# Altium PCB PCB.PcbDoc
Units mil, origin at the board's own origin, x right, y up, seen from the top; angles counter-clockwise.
Board outline 1889.76 x 2283.46 mil, 2 copper layers (Top Layer, Bottom Layer); 37 components, 25 nets, 145 pads, 86 vias.
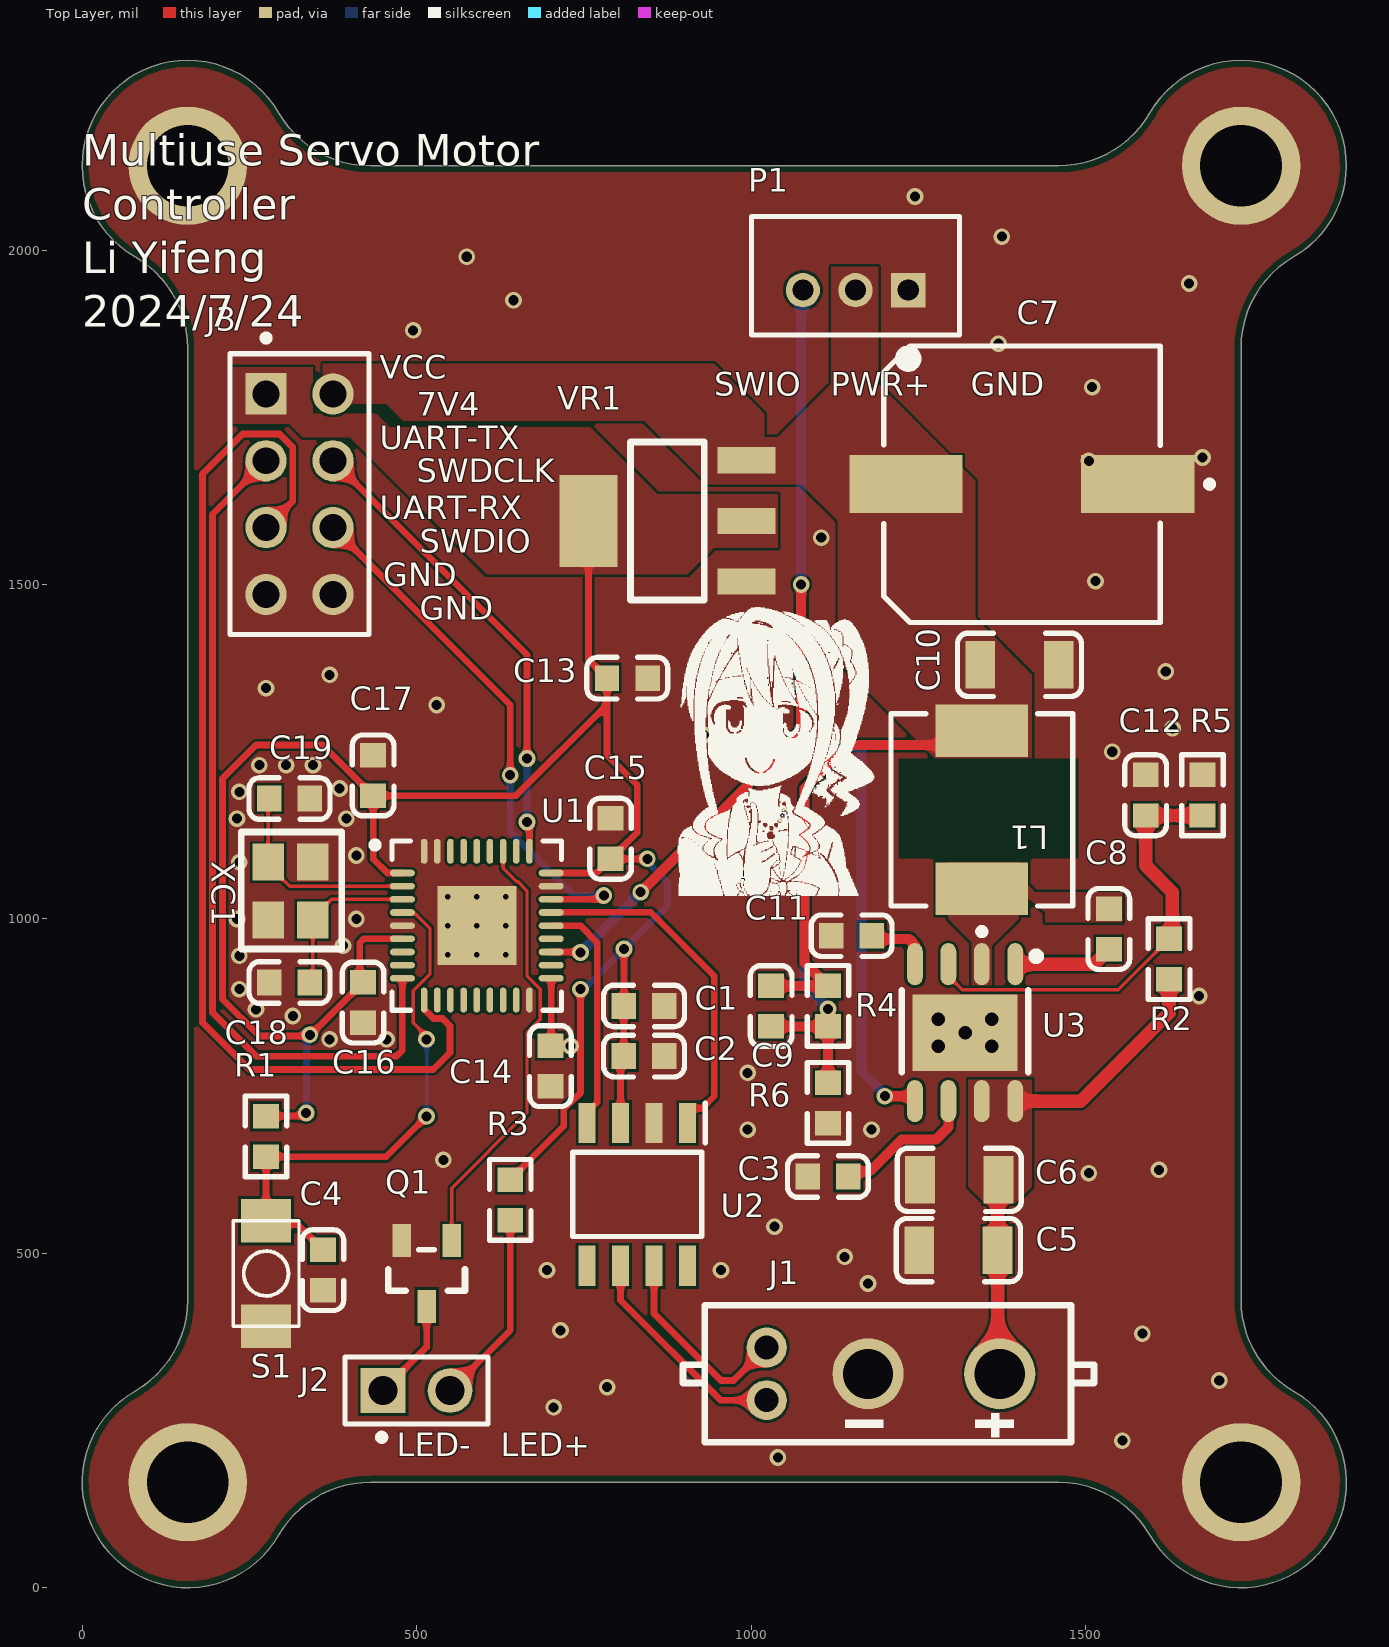
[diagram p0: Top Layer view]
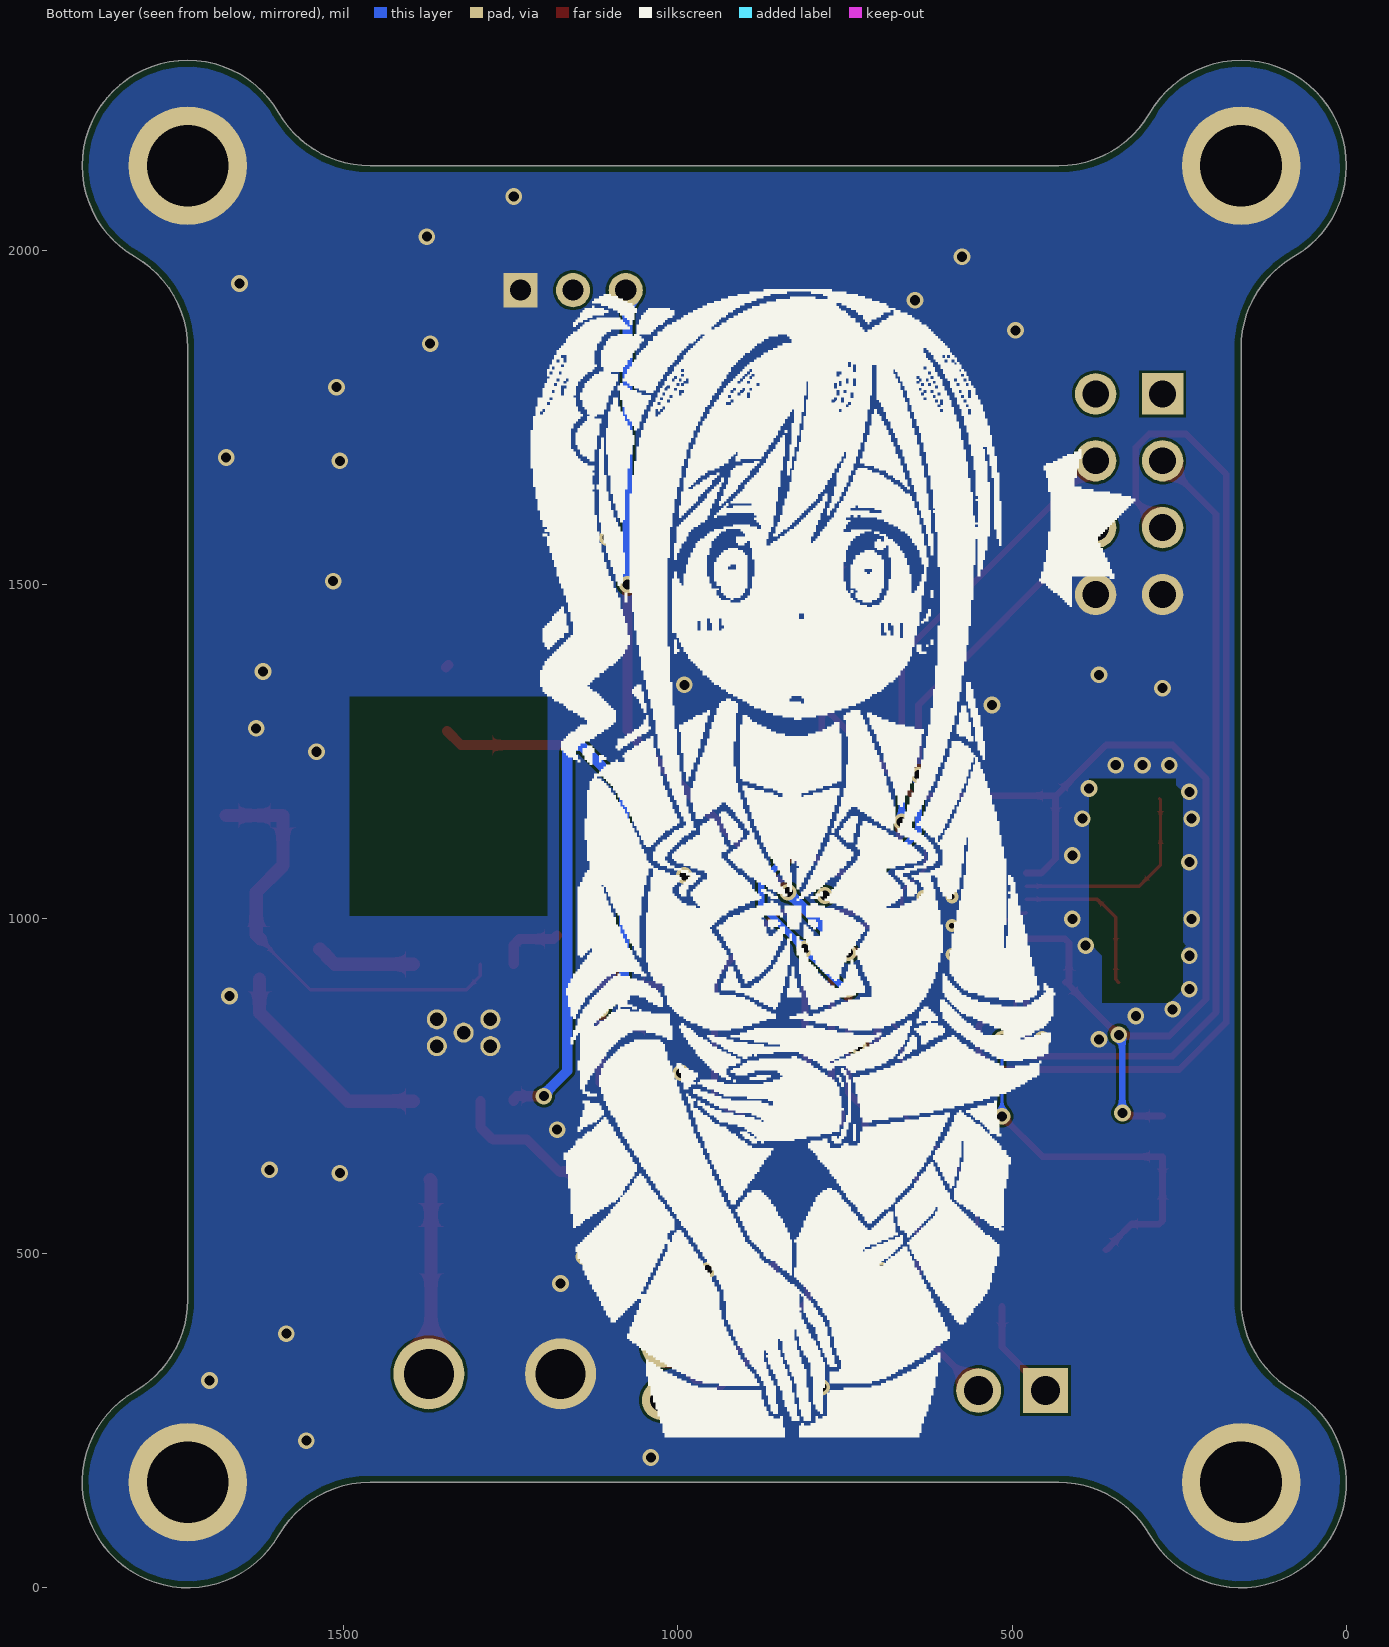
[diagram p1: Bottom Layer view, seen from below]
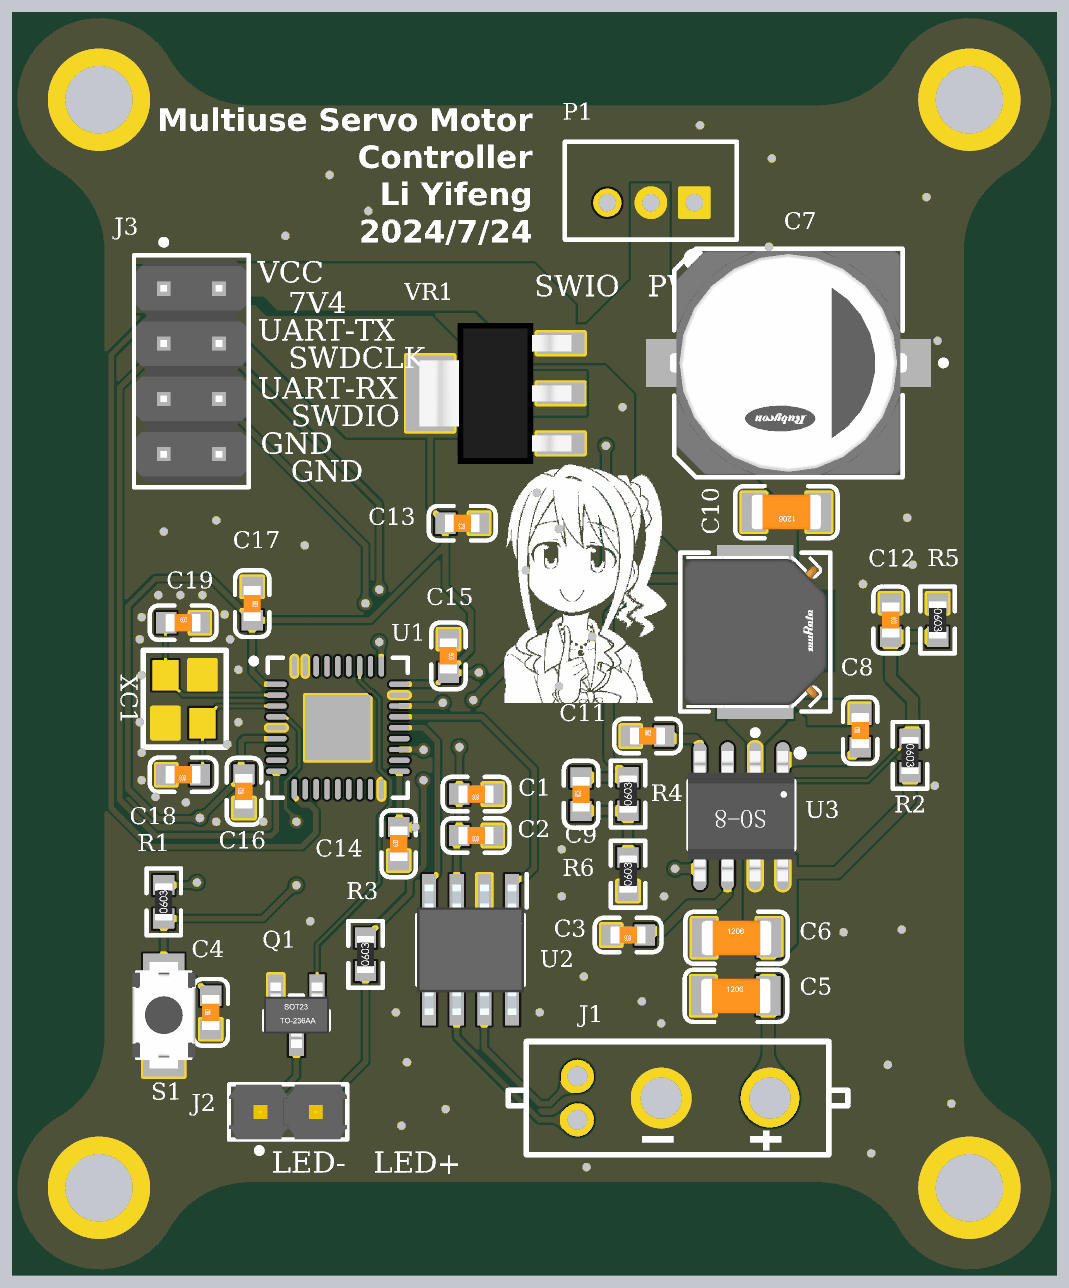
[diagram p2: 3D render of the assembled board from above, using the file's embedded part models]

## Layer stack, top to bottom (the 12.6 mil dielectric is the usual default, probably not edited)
Top Solder: solder mask 0.4, Solder Resist, Dk 3.5
Top Layer: signal copper 1.4
Dielectric 1: dielectric 12.6, FR-4, Dk 4.8
Bottom Layer: signal copper 1.4
Bottom Solder: solder mask 0.4, Solder Resist, Dk 3.5

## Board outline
294.11,78.99 cw(c157.73,157.73) 78.99,294.11 ccw(c0.25,430.49) 157.73,430.49 157.73,1853.47 ccw(c0.25,1853.47) 78.99,1989.85 cw(c157.73,2126.23) 294.11,2204.97 ccw(c430.49,2283.71) 430.49,2126.23 1459.77,2126.23 ccw(c1459.77,2283.71) 1596.15,2204.97 cw(c1732.53,2126.23) 1811.27,1989.85 ccw(c1890.01,1853.47) 1732.53,1853.47 1732.53,430.49 ccw(c1890.01,430.49) 1811.27,294.11 cw(c1732.53,157.73) 1596.15,78.99 ccw(c1459.77,0.25) 1459.77,157.73 430.49,157.73 ccw(c430.49,0.25)

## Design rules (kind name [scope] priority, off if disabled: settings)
BoardOutlineClearance BoardOutlineClearance_1 [All] p1: gap=10 ignorepadtopadclearanceinfootprint=FALSE except(0: Arc-SplitContinuation Track-SplitContinuation SMDPad-SplitContinuation THPad-SplitContinuation Via-SplitContinuation Fill-SplitContinuation Poly-SplitContinuation Region-SplitContinuation Text-SplitContinuation)
Clearance Clearance_1 [OnMid vs OnMid] p1: gap=4 ignorepadtopadclearanceinfootprint=FALSE sourcerule=42 cellrowname=All cellrowtype=0 cellcolname=All cellcoltype=0 innerlayers=TRUE
Clearance Clearance_2 [(ExistsOnLayer('Top Layer') Or ExistsOnLayer('Bottom Layer')) vs (ExistsOnLayer('Top Layer') Or ExistsOnLayer('Bottom Layer'))] p2: gap=4 ignorepadtopadclearanceinfootprint=FALSE sourcerule=42 cellrowname=All cellrowtype=0 cellcolname=All cellcoltype=0 outerlayers=TRUE
Clearance [All] p3: gap=10 ignorepadtopadclearanceinfootprint=FALSE ismatrix=TRUE
PolygonConnect [All] p1: connectstyle=Direct reliefconductorwidth=10 reliefentries=4 polygonreliefangle="90 Angle" airgapwidth=10
RoutingVias [All] p1: holewidth=15 width=25 viastyle="Through Hole" minholewidth=15 minwidth=25 maxholewidth=15 maxwidth=25
SolderMaskExpansion [All] p1: expansion=4 istentingtop=FALSE
SupplyNets "Schematic Supply Nets_3" [InNet('VCC')] p1: voltage=0.000
SupplyNets "Schematic Supply Nets_2" [InNet('7V4')] p2: voltage=0.000
SupplyNets "Schematic Supply Nets_1" [InNet('GND')] p3: voltage=0.000
SupplyNets "Schematic Supply Nets" [InNet('+24')] p4: voltage=0.000
Width "Schematic Width Constraint" [InNet('7V4')] p1: maxlimit=100 minlimit=5 preferedwidth=10 minimp=50.000000 maximp=50.000000 favimp=50.000000
Width [All] p2: maxlimit=100 minlimit=5 preferedwidth=10 minimp=50.000000 maximp=50.000000 favimp=50.000000
30 further rules are at their usual default settings.

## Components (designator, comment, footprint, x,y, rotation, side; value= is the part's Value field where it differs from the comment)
C1 "1uF (105) 10% 50V" 0603_C 840,870 r180 top
C2 "100nF (104) 10% 50V" 0603_C 840,795 r180 top
C3 "1uF (105) 10% 50V" 0603_C 1115,615 r180 top
C4 "100nF (104) 10% 50V" 0603_C 360,475 r90 top
C5 "10uF (106) 10% 50V" 1206_C 1310,505 r0 top
C6 "10uF (106) 10% 50V" 1206_C 1311.34,610 r0 top
C7 "50THV100M10X10.5" FP-THV10X10_5-MFG 1405,1650 r180 top
C8 "100nF (104) 10% 50V" 0603_C 1535,985 r90 top
C9 "100pF (101) 5% 50V" 0603_C 1030,869.68 r90 top
C10 "10uF (106) 10% 50V" 1206_C 1401.34,1380 r180 top
C11 "1uF (105) 10% 50V" 0603_C 1150.32,975 r0 top
C12 "1uF (105) 10% 50V" 0603_C 1590,1185 r270 top
C13 "1uF (105) 10% 50V" 0603_C 815,1360 r180 top
C14 "100nF (104) 10% 50V" 0603_C 700,780 r90 top
C15 "100nF (104) 10% 50V" 0603_C 790,1120 r270 top
C16 "100nF (104) 10% 50V" 0603_C 420,875 r90 top
C17 "100nF (104) 10% 50V" 0603_C 435,1214.68 r270 top
C18 "12pF (120) 5% 50V" 0603_C 310,905 r180 top
C19 "12pF (120) 5% 50V" 0603_C 310,1180 r0 top
J1 "XT30PB(2+2)-M" XT30PB(2+2)-M-Footprint-1 1262.61,332.36 r180 top
J2 "2211S-02G" FP-2211S-02G-MFG 500,295 r0 top
J3 "M20-9980446" FP-M20-9980446-MFG 325,1635 r270 top
L1 "FDSD0630-H-2R2M=P3" FP-FDSD0630-MFG 1345,1163.11 r90 top
P1 "B3B-PH-K-S(LF)(SN)" JST-B3B-PH-K-S-3_V 1156.26,1961.65 r180 top
Q1 "2N7002 7002" SOT-23(SOT-23-3) 515,470 r90 top
R1 "10KΩ (1002) ±1%" 0603_R 275,675 r90 top
R2 "10KΩ (1002) ±1%" 0603_R 1625,940 r270 top
R3 "1KΩ (1001) ±1%" 0603_R 640,580 r90 top
R4 "39KΩ (3902) ±1%" 0603_R 1115,870 r90 top
R5 "1KΩ (1001) ±1%" 0603_R 1675,1185 r270 top
R6 "3.3KΩ (3301) ±1%" 0603_R 1115,725 r90 top
S1 "按键" SWT3*4 275,470 r90 top
U1 "STM32F103TBU6" STM-VFQFPN36_L 590,990 r0 top
U2 "SN65HVD232D" SOIC127P600X175-8N 830,588.23 r270 top
U3 "SY8205FC" SOP-8_EP_150mil 1320,830 r180 top
VR1 "AMS1117-3.3" SOT-223 875,1595 r0 top
XC1 "3225 Passive Crystal" SMD-3225 278.07,1085 r270 top

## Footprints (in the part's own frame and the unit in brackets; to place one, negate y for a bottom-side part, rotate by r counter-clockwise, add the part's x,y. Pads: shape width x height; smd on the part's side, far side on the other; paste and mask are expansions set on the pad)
0603_C [mm]
  rect 0.93x0.98 smd: 1(-0.77,0) 2(0.77,0)
  silkscreen extent -1.53,-0.79 1.54,0.79, body extent -0.8,-0.4 0.8,0.4, height 0.3
0603_R [mm]
  rect 0.93x0.98 smd: 1(-0.77,0) 2(0.77,0)
  silkscreen extent -1.53,-0.79 1.54,0.79, body extent -0.85,-0.4 0.85,0.4, height 0.56
1206_C [mm]
  rect 1.13x1.8 smd: 1(-1.49,0) 2(1.49,0)
  silkscreen extent -2.36,-1.2 2.35,1.2, body extent -1.6,-0.81 1.6,0.79, height 1
FP-2211S-02G-MFG [mm]
  rect 1.7x1.7 hole 1.1 paste-2539.97 mask+0: 1(-1.27,0)
  round 1.7 hole 1.1 paste-2539.97 mask+0: 2(1.27,0)
  silkscreen extent -2.72,-1.9 2.72,1.27, body extent -2.82,-1.37 2.82,1.37, height 0.25
FP-FDSD0630-MFG [mm]
  rect 2x3.5 smd paste+0 mask+0: 1(-3,0) 2(3,0)
  silkscreen extent -4.75,-3.45 3.65,3.45, body extent -4.1,-3.55 4.1,3.55, height 0.25
FP-M20-9980446-MFG [mm]
  rect 1.57x1.57 hole 1.02 paste-2539.97 mask+0: 1(-3.81,-1.27)
  round 1.57 hole 1.02 paste-2539.97 mask+0: 2(-3.81,1.27) 3(-1.27,-1.27) 4(-1.27,1.27) 5(1.27,-1.27) 6(1.27,1.27) 7(3.81,-1.27) 8(3.81,1.27)
  silkscreen extent -6.05,-2.64 5.33,2.64, body extent -5.43,-2.74 5.43,2.74, height 0.25
FP-THV10X10_5-MFG [mm]
  rect 4.3x2.2 smd paste+0 mask+0: 1(-4.4,0) 2(4.4,0)
  silkscreen extent -7.25,-5.25 5.25,5.25, body extent -6.8,-5.5 6.8,5.5, height 0.25
JST-B3B-PH-K-S-3_V [mm] "Connector, 3-Leads, Body 7.9x4.5mm, Pitch 2mm"
  rect 1.3x1.3 hole 0.8: 1(-2,0.55)
  round 1.3 hole 0.8: 2(0,0.55) 3(2,0.55)
  silkscreen extent -3.95,-2.25 3.95,3.4, body extent -3.95,-2.25 3.95,2.25, height 6
SMD-3225 [mm]
  rect 1.4x1.2 smd paste-2539.97: 1(0,0) 2(2.2,0) 3(2.2,1.7) 4(0,1.7)
  silkscreen extent -1.14,-1.02 3.3,2.79
SOIC127P600X175-8N [mm]
  rect 1.525x0.65 smd: 1(-2.712,1.905) 2(-2.712,0.635) 3(-2.712,-0.635) 4(-2.712,-1.905) 5(2.712,-1.905) 6(2.712,-0.635) 7(2.712,0.635) 8(2.712,1.905)
  silkscreen extent -3.47,-2.45 1.6,2.58, body extent -3,-2.45 3,2.45, height 1.75
SOP-8_EP_150mil [mm]
  round 0.762 hole 0.508: 0(-1.016,-0.508) 0(-1.016,0.508) 0(0,0) 0(1.016,0.508) 0(1.016,-0.508)
  rect 4x2.9 smd: 0(0,0)
  oval 0.6x1.6 smd: 1(-1.905,-2.6) 2(-0.635,-2.6) 3(0.635,-2.6) 4(1.905,-2.6) 5(1.905,2.6) 6(0.635,2.6) 7(-0.635,2.6) 8(-1.905,2.6)
  silkscreen extent -2.85,-3.05 2.4,1.5, body extent -2.45,-3 2.45,3
SOT-23(SOT-23-3) [mm]
  rect 1.25x0.7 smd: 1(1.25,-0.95) 2(1.25,0.95) 3(-1.25,0)
  silkscreen extent -0.65,-1.46 0.9,1.46, body extent -1.5,-1.5 1.5,1.5, height 1.3
SOT-223 [mm]
  rect 2.2x1 smd: 1(3,-2.3) 2(3,0) 3(3,2.3)
  rect 2.2x3.5 smd: 2(-3,0)
  silkscreen extent -1.4,-3 1.4,3, body extent -3.49,-3.24 3.49,3.24, height 1.64
STM-VFQFPN36_L [mm] "QFN, 36-Leads, Body 6.13x6.13mm, Pitch 0.5mm, Thermal Pad 3x3mm, IPC High Density"
  oval 0.95x0.25 smd: 1(-2.825,2) 2(-2.825,1.5) 3(-2.825,1) 4(-2.825,0.5) 5(-2.825,0) 6(-2.825,-0.5) 7(-2.825,-1) 8(-2.825,-1.5) 9(-2.825,-2) 19(2.825,-2) 20(2.825,-1.5) 21(2.825,-1) 22(2.825,-0.5) 23(2.825,0) 24(2.825,0.5) 25(2.825,1) 26(2.825,1.5) 27(2.825,2)
  oval 0.25x0.95 smd: 10(-2,-2.825) 11(-1.5,-2.825) 12(-1,-2.825) 13(-0.5,-2.825) 14(0,-2.825) 15(0.5,-2.825) 16(1,-2.825) 17(1.5,-2.825) 18(2,-2.825) 28(2,2.825) 29(1.5,2.825) 30(1,2.825) 31(0.5,2.825) 32(0,2.825) 33(-0.5,2.825) 34(-1,2.825) 35(-1.5,2.825) 36(-2,2.825)
  rect 3x3 smd: 37(0,0)
  silkscreen extent -3.99,-3.21 3.21,3.21, body extent -3.07,-3.07 3.07,3.07, height 1
SWT3*4 [mm]
  rect 1.65x1.9 smd: 1(-2,0) 2(2,0)
  silkscreen extent -2,-1.25 2,1.25, body extent -2.45,-1.45 2.45,1.45, height 2
XT30PB(2+2)-M-Footprint-1 [mil]
  round 106.3 hole 74.8 paste-99999 mask+1.97: 1(-109.24,12.36) 2(87.61,12.36)
  round 60 hole 35.98 paste-99999 mask+1.97: 3(239.18,-27.01) 4(239.18,51.73)
  silkscreen extent -250,-90 364,115

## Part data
C1 C3 C11 C12 C13: library part "0603 1uF (105) 10% 50V", "贴片电容", Package=0603, SuppliersPartNumber=C15849
C2 C4 C8 C14 C15 C16 C17: library part "0603 100nF (104) 10% 50V", "贴片电容", Package=0603, SuppliersPartNumber=C14663
C5 C6 C10: library part "1206 10uF (106) 10% 50V", "贴片电容", Package=1206, SuppliersPartNumber=C13585
C7: library part CMP-35376-000015-1, "CAP ALUM 100UF 20% 50V SMD", Capacitance=100uF, Case/Package=Radial, ESR (Equivalent Series Resistance)=250mR, Max Operating Temperature=125°C, Min Operating Temperature=-40°C, Package Quantity=1, Ripple Current=175mA, Ripple Current (AC)=350mA, Tolerance=20%, Voltage=50V
C9: library part "0603 100pF (101) 5% 50V", "贴片电容", Package=0603, SuppliersPartNumber=C14858
C18 C19: library part "0603 12pF (120) 5% 50V", "贴片电容", Package=0603, SuppliersPartNumber=C38523
J1: library part CMP-002-00072-5, "This is a power connector that can also be used to send/receive can signals"
J2: library part CMP-12414-000006-2, "2.54mm pitch, single row PCB headers.", Flammability Rating="UL94 V-0", Insulation Resistance=1GR
J3: library part CMP-15831-000088-1, "CONN HEADER VERT 8POS 2.54MM", Color=Black, Contact Resistance=30mR, Current Rating=3A, Flammability Rating="UL94 V-0", Insulation Resistance=10GR, Max Operating Temperature=105°C, Min Operating Temperature=-40°C, Package Quantity=1000
L1: library part CMP-06042-016400-1, "FIXED IND 2.2UH 7.1A 17 MOHM SMD", Case/Package=Nonstandard, Current Rating=7.1A, DC Resistance (DCR)=17mR, Inductance=2.2uH, Resistor Type=Wirewound, Saturation Current=12A, Test Frequency=100kHz, Tolerance=20%
P1: library part CMP-2000-05164-1, "Male Header, Pitch 2 mm, 1 x 3 Position, Height 6 mm, Tail Length 3.4 mm, -25 to 85 degC, RoHS, Bulk", Manufacturer=JST
Q1: "MOS(场效应管)", Package=SOT-23(SOT-23-3), SuppliersPartNumber=C8545
R1 R2: library part "0603 10KΩ (1002) 1%", "贴片电阻", Package=0603, SuppliersPartNumber=C25804
R3 R5: library part "0603 1KΩ (1001) 1%", "贴片电阻", Package=0603, SuppliersPartNumber=C21190
R4: library part "0603 39KΩ (3902) 1%", "贴片电阻", Package=0603, SuppliersPartNumber=C23153
R6: library part "0603 3.3KΩ (3301) 1%", "贴片电阻", Package=0603, SuppliersPartNumber=C22978
S1: library part Button
U1: library part CMP-0237-00055-3, "ARM Cortex-M3 32-bit MCU, 128 KB Flash, 20 KB Internal RAM, 26 I/Os, 36-pin VFQFPN, -40 to 85 degC, Tray", I/Os (High Current)=26, Operating Frequency(F) (Processor speed) (MHz)=72, Supply Voltage(Vcc) min (V)=2
U2: "3.3-V CAN TRANSCEIVER", Manufacturer_Name="Texas Instruments", Mouser Part Number=595-SN65HVD232D, RS Part Number=1977506
U3: "5A, 4.5V-30V Input, Synchronous Step Down Regulator (Buck)"
VR1: library part "SOT-223 AMS1117-3.3", "低压差线性稳压(LDO)", Package=SOT-223, SuppliersPartNumber=C6186

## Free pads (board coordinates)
  round 177.17 hole 122.05 paste-99999: 41(157.73,157.73) 42(1732.53,157.73) 44(157.73,2126.23) 45(1732.53,2126.23)

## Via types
v1: diameter 25, hole 15, Top Layer to Bottom Layer, tented both sides, 77 vias
v2: diameter 19.68, hole 7.87, Top Layer to Bottom Layer, 9 vias

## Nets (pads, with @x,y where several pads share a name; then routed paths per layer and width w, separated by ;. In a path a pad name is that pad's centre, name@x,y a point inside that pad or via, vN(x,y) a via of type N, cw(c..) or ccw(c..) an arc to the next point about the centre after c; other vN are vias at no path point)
3V3_LDO: C3.1 U3.6 | length 219.1
  Top Layer w15: C3.1 1152.65,622.34 1177.34,622.34 1225,670 1276.21,670 1295,688.79 U3.6
7V4: C7.2 C9.2 C10.2 J3.2 L1.2 P1.2 R4.2 VR1.3 | length 700.8
  Top Layer w15: C9.2 1114.68,900 R4.2 1114.02,900.32 1080,934.33 1080,1195 1145,1260 1323.78,1260 L1.2 ; C10.2 C10.2@1346.34,1376.34
+24: C5.2 C6.2 J1.1 R2.2 U3.7 U3.8 | length 649
  Top Layer w15: J1.1 J1.1@1371.85,342.59
  Top Layer w20: C6.2 1368.66,608.66 C5.2 1368.66,323.19 J1.1 ; U3.8 1492.64,727.64 1625,860 R2.2
BS: C8.1 U3.1 | length 149.8
  Top Layer w20: U3.1 1512.68,932.36 1525.71,945.39 1525.71,946.38 1534.02,954.68 C8.1
CAN_N: J1.4 U2.6 | length 331.8
  Top Layer w10: U2.6 805,430 954.37,280.63 J1.4
CAN_P: J1.3 U2.7 | length 307.5
  Top Layer w10: U2.7 855,410 955,310 974.07,310 J1.3
  Top Layer w15: U2.7 U2.7@859.09,477.37
CAND: U1.24 U2.1 | length 528.1
  Top Layer w10: U1.24 714.84,1009.69 715.16,1010 850,1010 945,915 945,735 926.94,716.94 912.79,716.94 905,709.14 U2.1
CANR: U1.23 U2.4 | length 356.1
  Top Layer w10: U1.23 745,990 770,965 770,725.88 764.14,720.02 762.8,720.02 755,712.22 U2.4
EN_DCDC: C12.2 R2.1 R5.2 U3.3 | length 675.4
  Top Layer w5: U3.3 1295,915 1315.63,894.37 1549.05,894.37 1608.21,953.52 1608.21,954.51 R2.1@1624.02,970.31
  Top Layer w20: R2.1@1624.02,970.31 1630,976.3 1630,1040 1590,1080 C12.2 R5.2
FB: C9.1 R4.1 R6.2 U3.5 | length 1233.9
  Top Layer w15: C9.1 1114.68,839.37 R4.1 ; R6.2 R4.1 ; v1(1115,865.51) R4.1 ; v1(1200,735) 1241.02,735 1245,731.02 U3.5
  Bottom Layer w15: v1(1115,865.51) 1080,900.51 1080,1195 1143.79,1258.79 1156.21,1258.79 1165,1250 1165,772.71 1200,737.71 v1(1200,735)
GND: C1.1 C2.1 C3.2 C4.1 C5.1 C6.1 C7.1 C10.1 C11.1 C12.1 C13.1 C14.1 C15.1 C16.1 C17.1 C18.2 C19.2 J1.2 J3.7 J3.8 P1.1 pad.41 pad.42 pad.44 pad.45 Q1.2 R5.1 R6.1 S1.1 U1.5 U1.18 U1.26 U1.35 U1.36 U1.37 U2.2 U3.0 VR1.1 XC1.2 XC1.4
  other v1: 1040,195 1555,220 705,270 785,300 1700,310 1585,380 715,385 1175,455 695,475 955,475 1140,495 1035,540 1505,620 1610,625 540,640 995,685 1180,685 995,770 370,820 455,820 315,855 260,865 1670,885 235,895 235,945 390,960 231.5,1000 410,1000 990,1065 235,1085 410,1095 231.5,1150 395,1150 1050,1155 235,1190 385,1195 265,1230 305,1230 345,1230 1540,1250 930,1275 1630,1285 530,1320 275,1345 990,1350 370,1365 1620,1370 950,1415 1515,1505 1105,1570 1505,1685 1675,1690 1510,1795 1370,1860 495,1880 645,1925 1655,1950 575,1990 1375,2020 1245,2080
  other v2: 546.69,946.69 590,946.69 633.31,946.69 546.69,990 590,990 633.31,990 546.69,1033.31 590,1033.31 633.31,1033.31
LED_N: J2.1 Q1.3 | length 152.7
  Top Layer w10: J2.1 515,360 Q1.3
LED_P: J2.2 R3.1 | length 292
  Top Layer w10: J2.2 640,385 R3.1
LEDCTRL: Q1.1 U1.30 | length 661.3
  Top Layer w5: Q1.1 552.4,597.4 665,710 665,830 685,850 685,895 665,915 665,1042.3 651.75,1055.56 649.44,1055.56 629.37,1075.63 U1.30
LX: C8.2 L1.1 U3.2
NetC4_2: C4.2 R1.1 S1.2 U1.4 | length 815.1
  Top Layer w5: U1.4 479.71,1008.76 497.07,1008.76 520,985.82 520,917.45 495,892.45 495,844.64 515,824.64 v1(515,820)
  Top Layer w10: C4.2 359.02,505.31 345.71,518.62 345.71,519.61 321.54,543.77 279.97,543.77 S1.2 R1.1 454.69,644.69 v1(515,705)
  Bottom Layer w5: v1(515,705) v1(515,820)
NetC18_1: C18.1 U1.3 XC1.3 | length 244.2
  Top Layer w5: C18.1 345,909.68 XC1.3 345,1002.32 366.12,1023.44 366.87,1023.44 372.79,1029.37 U1.3
NetC19_1: C19.1 U1.2 XC1.1 | length 313.6
  Top Layer w5: C19.1 278.07,1178.39 XC1.1 278.07,1081.06 310.08,1049.06 U1.2
SS_DCDC: C11.2 U3.4 | length 98.9
  Top Layer w15: C11.2 1185.63,970 1236.21,970 1245,961.21 U3.4
SWDCK: J3.4 U1.28 | length 705.5
  Top Layer w10: J3.4 665,1395 v1(665,1240) ; v1(665,1145) 665,1140.94 668.74,1137.2 U1.28
  Bottom Layer w10: v1(665,1145) v1(665,1240)
SWDIO: J3.6 U1.25 | length 825.2
  Top Layer w10: J3.6 640,1320 v1(640,1215) ; U1.25 770.31,1029.37 775.94,1035 v1(780,1035)
  Bottom Layer w10: v1(640,1215) 640,1130 735,1035 v1(780,1035)
SWIO: P1.3 U1.21 | length 1171.8
  Top Layer w5: v1@744.37,950.63 v1(745,950)
  Top Layer w10: U1.21 v1@744.37,950.63
  Top Layer w15: v1(835,1040) 1061,1266 1061,1267.87 1075,1281.87 v1(1075,1500)
  Bottom Layer w5: P1.3@1075,1937.48 P1.3
  Bottom Layer w15: v1(745,950) v1(835,1040) ; v1(1075,1500) P1.3@1075,1937.48
UART_RX: J3.5 U1.10 | length 1623.2
  Top Layer w10: J3.5 315,1625 315,1705 295,1725 240,1725 180,1665 180,845 250,775 525,775 550,800 550,840.04 538.96,851.08 525.18,851.08 517.02,859.23 517.02,859.39 U1.10@511.34,865.08
UART_TX: J3.3 U1.9 | length 1279.8
  Top Layer w10: J3.3 195,1605 195,860.2 260.2,795 470,795 478.78,803.78 U1.9
VCC: C1.2 C2.2 C13.2 C14.2 C15.2 C16.2 C17.2 J3.1 R1.2 R3.2 U1.1 U1.6 U1.19 U1.27 U2.3 VR1.2 | length 3408.3
  Top Layer w10: R1.2 v1@326.26,705.32 ; v1@335.38,827.1 333.28,825 265,825 210,880 210,1210 260,1260 359.37,1260 420.71,1198.66 420.71,1197.68 434.02,1184.37 C17.2 ; v1(340.38,826.78) 341.47,826.78 405.71,891.02 405.71,892.01 419.02,905.32 C16.2 ; C16.2@415,905.63 415,964.46 420.86,970.32 U1.6 ; U1.1 456.26,1068.74 435,1090 C17.2 ; R3.2 640.98,610.32 654.29,623.62 654.29,624.61 720,690.32 720,715.54 738.48,734.02 739.02,734.02 745,740 v1(745,895) ; U1.19 701.22,811.54 C14.2 700.32,810 v1(730,810) ; U1.27 769.06,1068.74 775.71,1075.39 775.71,1076.38 789.02,1089.68 C15.2 C15.2@790.98,1089.68 ; VR1.2@756.89,1595 756.89,1387.8 770.39,1374.29 771.38,1374.29 784.68,1360.98 C13.2 784.68,1320.32 ; U2.3 805,790.31 C2.2 C1.2 810,870.32 v1(810,955) ; v1(845,1090) 844.68,1089.68 C15.2@790.98,1089.68 ; C17.2 648.74,1184.37 784.68,1320.32 ; 784.68,1320.32 784.68,1245.32 830,1200 830,1129.68 804.29,1103.98 804.29,1102.99 C15.2@790.98,1089.68
  Bottom Layer w10: v1(335,710) 335.38,710.38 v1@335.38,827.1 ; v1(745,895) 749.06,895 756,901.95 756.95,901.95 v1(810,955) 875,1020 875,1055 851.95,1078.05 851.95,1079 845,1085.94 v1(845,1090)
pads on no net: U1.7 U1.8 U1.11 U1.12 U1.13 U1.14 U1.15 U1.16 U1.17 U1.20 U1.22 U1.29 U1.31 U1.32 U1.33 U1.34 U2.5 U2.8

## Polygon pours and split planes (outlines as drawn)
GND on Top Layer "GND_L01_P011" (solid, pour order 11): 1927.51,2422.62 1927.51,2.62 2.51,2.62 2.51,2402.62
LX on Top Layer "LX_L01_P002" (solid, pour order 2): 1330,900 1330,965 1295,1000 1295,1085 1400,1085 1400,1065 1425,1040 1555,1040 1555,995 1440,995 1440,1010 1415,1030 1405,1030 1400,1025 1400,1000 1360,960 1360,900
7V4 on Top Layer "7V4_L01_P006" (solid, pour order 6): 360,1830 360,1770 455,1770 480,1745 840,1745 935,1650 1020,1650 1020,1755 945,1830
VCC on Top Layer "VCC_L01_P005" (solid, pour order 5): 225,1825 225,1740 310,1740 330,1720 400,1720 605,1515 905,1515 945,1555 1040,1555 1040,1635 860,1635 760,1735 460,1735 440,1755 345,1755 345,1825
7V4 on Top Layer "7V4_L01_P003" (solid, pour order 3): 1280,1235 1130,1385 1130,1595 1075,1650 945,1650 935,1660 940,1665 940,1720 1040,1720 1120,1800 1120,1905 1120,1975 1190,1975 1190,1800 1335,1655 1335,1450 1420,1365 1420,1235
+24 on Top Layer "+24_L01_P000" (solid, pour order 0): 1325,760 1325,600 1350,575 1395,575 1420,600 1420,760
GND on Bottom Layer "GND_L02_P012" (solid, pour order 12): 0,2530 0,0 2030,0 2030,2495

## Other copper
Top Layer:
  pour cut-out: 1220,1240 1220,1090 1490,1090 1490,1240
Bottom Layer:
  pour cut-out: 1195,1332.5 1195,1005 1490,1005 1490,1332.5
  pour cut-out: 365,875 365,945 385,965 385,1210 255,1210 255,1200 245,1190 245,965 240,960 245,955 245,895 265,875

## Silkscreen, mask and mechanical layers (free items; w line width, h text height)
Top Overlay:
  drawing of 66 lines, arcs and shapes, not listed
  text "Multiuse Servo Motor / Controller / Li Yifeng / 2024/7/24" at 0,1870 h80
  text "VCC" at 445,1795.61 h60
  text "SWIO   PWR+    GND" at 945,1770.61 h60
  text "7V4" at 500,1740 h60
  text "UART-TX" at 445,1690.61 h60
  text "SWDCLK" at 500,1640.61 h60
  text "UART-RX" at 445,1585.61 h60
  text "SWDIO" at 505,1535.61 h60
  text "GND" at 450,1485.61 h60
  text "GND" at 505,1435.61 h60
  text "LED-   LED+" at 470,185 h60
Bottom Overlay:
  drawing of 100 lines, arcs and shapes, not listed
Mechanical 1:
  the board outline again, w0.5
